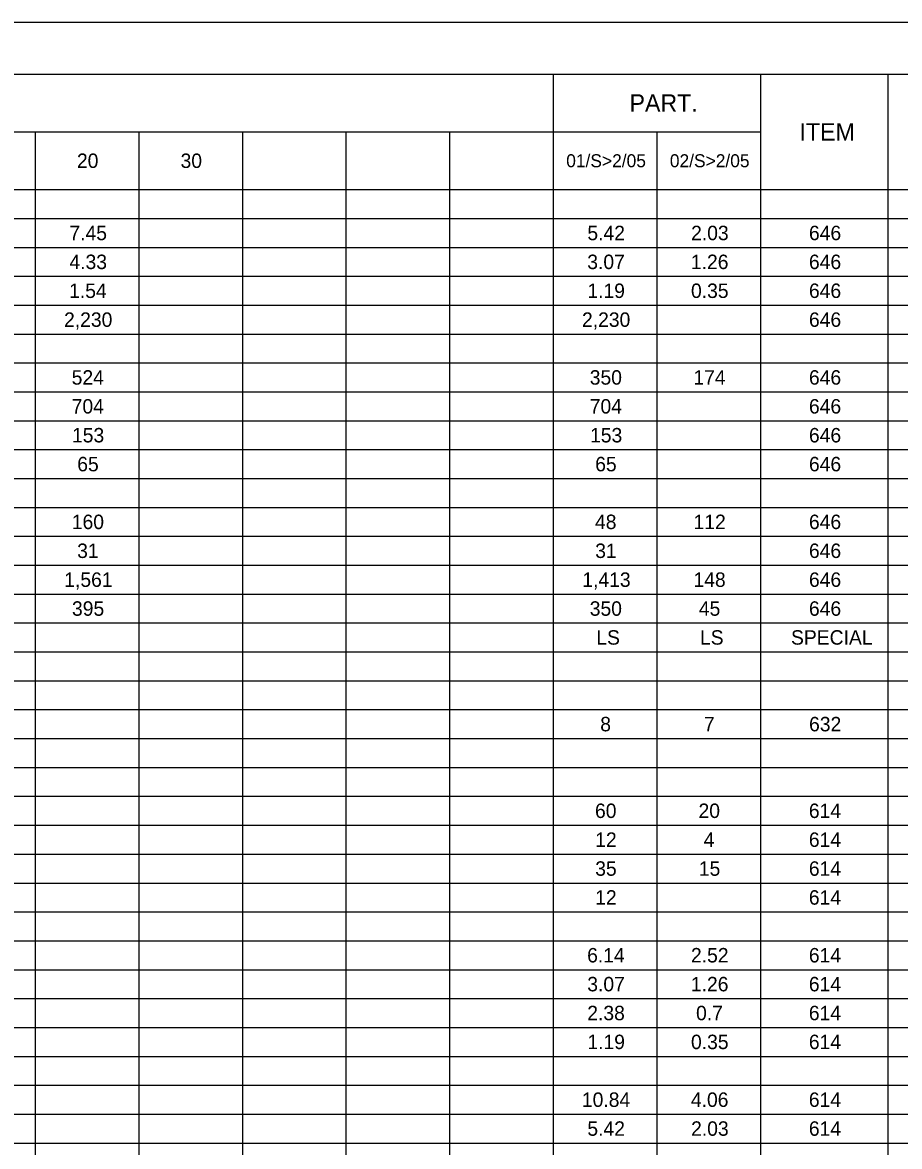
# Model space of a CAD drawing. Extents: x 0 to 34, y 0 to 22.
# Drawn here: x 8.41 to 16.92, y 11.11 to 22 of the extents above; entities that cross this region are included whole.
import ezdxf

# ---------------------------------------------------------------- set-up
doc = ezdxf.new("R2010")
doc.units = 0
for name, color, linetype in [('SH_Border', 7, 'Continuous'), ('SH_Cut_Line', 7, 'Continuous'), ('SH_Text', 7, 'Continuous')]:
    doc.layers.add(name, color=color, linetype=linetype)

msp = doc.modelspace()

# ---------------------------------------------------------------- linework, layer by layer
at = {"layer": 'SH_Border'}
msp.add_lwpolyline([(1.5, 21.5), (33.5, 21.5), (33.5, 0.5), (1.5, 0.5)], close=True, dxfattribs=at)
at = {"layer": 'SH_Cut_Line'}
msp.add_lwpolyline([(0, 0), (34, 0), (34, 22), (0, 22)], close=True, dxfattribs=at)
at = {"layer": 'SH_Text'}
for p, q in [((1.5, 21.5), (32.004, 21.5)), ((13.556, 21.5), (13.556, 0.5)), ((15.566, 21.5), (15.566, 0.5)), ((16.801, 21.5), (16.801, 0.5)), ((1.5, 20.94), (15.566, 20.94)), ((8.533, 20.94), (8.533, 0.5)), ((9.538, 20.94), (9.538, 0.5)), ((10.542, 20.94), (10.542, 0.5)), ((11.547, 20.94), (11.547, 0.5)), ((12.552, 20.94), (12.552, 0.5)), ((14.561, 20.94), (14.561, 0.5)), ((1.5, 20.38), (32.004, 20.38)), ((1.5, 20.1), (32.004, 20.1)), ((1.5, 19.82), (32.004, 19.82)), ((1.5, 19.54), (32.004, 19.54)), ((1.5, 19.26), (32.004, 19.26)), ((1.5, 18.98), (32.004, 18.98)), ((1.5, 18.7), (32.004, 18.7)), ((1.5, 18.42), (32.004, 18.42)), ((1.5, 18.14), (32.004, 18.14)), ((1.5, 17.86), (32.004, 17.86)), ((1.5, 17.58), (32.004, 17.58)), ((1.5, 17.3), (32.004, 17.3)), ((1.5, 17.02), (32.004, 17.02)), ((1.5, 16.74), (32.004, 16.74)), ((1.5, 16.46), (32.004, 16.46)), ((1.5, 16.18), (32.004, 16.18)), ((1.5, 15.9), (32.004, 15.9)), ((1.5, 15.62), (32.004, 15.62)), ((1.5, 15.34), (32.004, 15.34)), ((1.5, 15.06), (32.004, 15.06)), ((1.5, 14.78), (32.004, 14.78)), ((1.5, 14.5), (32.004, 14.5)), ((1.5, 14.22), (32.004, 14.22)), ((1.5, 13.94), (32.004, 13.94)), ((1.5, 13.66), (32.004, 13.66)), ((1.5, 13.38), (32.004, 13.38)), ((1.5, 13.1), (32.004, 13.1)), ((1.5, 12.82), (32.004, 12.82)), ((1.5, 12.54), (32.004, 12.54)), ((1.5, 12.26), (32.004, 12.26)), ((1.5, 11.98), (32.004, 11.98)), ((1.5, 11.7), (32.004, 11.7)), ((1.5, 11.42), (32.004, 11.42)), ((1.5, 11.14), (32.004, 11.14))]:
    msp.add_line(p, q, dxfattribs=at)

# ---------------------------------------------------------------- texts
for s, height, p in [('PART.', 0.168, (14.297, 21.136)), ('ITEM', 0.168, (15.945, 20.856)), ('20', 0.14, (8.938, 20.59)), ('30', 0.14, (9.943, 20.59)), ('01/S>2/05', 0.126, (13.683, 20.597)), ('02/S>2/05', 0.126, (14.688, 20.597)), ('7.45', 0.14, (8.865, 19.89)), ('5.42', 0.14, (13.888, 19.89)), ('2.03', 0.14, (14.894, 19.89)), ('646', 0.14, (16.037, 19.89)), ('4.33', 0.14, (8.865, 19.61)), ('3.07', 0.14, (13.887, 19.61)), ('1.26', 0.14, (14.892, 19.61)), ('646', 0.14, (16.037, 19.61)), ('1.54', 0.14, (8.862, 19.33)), ('1.19', 0.14, (13.888, 19.33)), ('0.35', 0.14, (14.893, 19.33)), ('646', 0.14, (16.037, 19.33)), ('2,230', 0.14, (8.813, 19.05)), ('2,230', 0.14, (13.836, 19.05)), ('646', 0.14, (16.037, 19.05)), ('524', 0.14, (8.887, 18.49)), ('350', 0.14, (13.911, 18.49)), ('174', 0.14, (14.916, 18.49)), ('646', 0.14, (16.037, 18.49)), ('704', 0.14, (8.887, 18.21)), ('704', 0.14, (13.911, 18.21)), ('646', 0.14, (16.037, 18.21)), ('153', 0.14, (8.89, 17.93)), ('153', 0.14, (13.914, 17.93)), ('646', 0.14, (16.037, 17.93)), ('65', 0.14, (8.941, 17.65)), ('65', 0.14, (13.964, 17.65)), ('646', 0.14, (16.037, 17.65)), ('160', 0.14, (8.888, 17.09)), ('48', 0.14, (13.962, 17.09)), ('112', 0.14, (14.918, 17.09)), ('646', 0.14, (16.037, 17.09)), ('31', 0.14, (8.94, 16.81)), ('31', 0.14, (13.964, 16.81)), ('646', 0.14, (16.037, 16.81)), ('1,561', 0.14, (8.815, 16.53)), ('1,413', 0.14, (13.839, 16.53)), ('148', 0.14, (14.917, 16.53)), ('646', 0.14, (16.037, 16.53)), ('395', 0.14, (8.89, 16.25)), ('350', 0.14, (13.911, 16.25)), ('45', 0.14, (14.969, 16.25)), ('646', 0.14, (16.037, 16.25)), ('LS', 0.14, (13.975, 15.97)), ('LS', 0.14, (14.98, 15.97)), ('SPECIAL', 0.14, (15.863, 15.97)), ('8', 0.14, (14.013, 15.13)), ('7', 0.14, (15.018, 15.13)), ('632', 0.14, (16.038, 15.13)), ('60', 0.14, (13.962, 14.29)), ('20', 0.14, (14.966, 14.29)), ('614', 0.14, (16.036, 14.29)), ('12', 0.14, (13.964, 14.01)), ('4', 0.14, (15.016, 14.01)), ('614', 0.14, (16.036, 14.01)), ('35', 0.14, (13.964, 13.73)), ('15', 0.14, (14.969, 13.73)), ('614', 0.14, (16.036, 13.73)), ('12', 0.14, (13.964, 13.45)), ('614', 0.14, (16.036, 13.45)), ('6.14', 0.14, (13.886, 12.89)), ('2.52', 0.14, (14.893, 12.89)), ('614', 0.14, (16.036, 12.89)), ('3.07', 0.14, (13.887, 12.61)), ('1.26', 0.14, (14.892, 12.61)), ('614', 0.14, (16.036, 12.61)), ('2.38', 0.14, (13.887, 12.33)), ('0.7', 0.14, (14.942, 12.33)), ('614', 0.14, (16.036, 12.33)), ('1.19', 0.14, (13.888, 12.05)), ('0.35', 0.14, (14.893, 12.05)), ('614', 0.14, (16.036, 12.05)), ('10.84', 0.14, (13.835, 11.49)), ('4.06', 0.14, (14.892, 11.49)), ('614', 0.14, (16.036, 11.49)), ('5.42', 0.14, (13.888, 11.21)), ('2.03', 0.14, (14.894, 11.21)), ('614', 0.14, (16.036, 11.21))]:
    msp.add_text(s, height=height, dxfattribs=at).set_placement(p)

doc.saveas('drawing.dxf')
